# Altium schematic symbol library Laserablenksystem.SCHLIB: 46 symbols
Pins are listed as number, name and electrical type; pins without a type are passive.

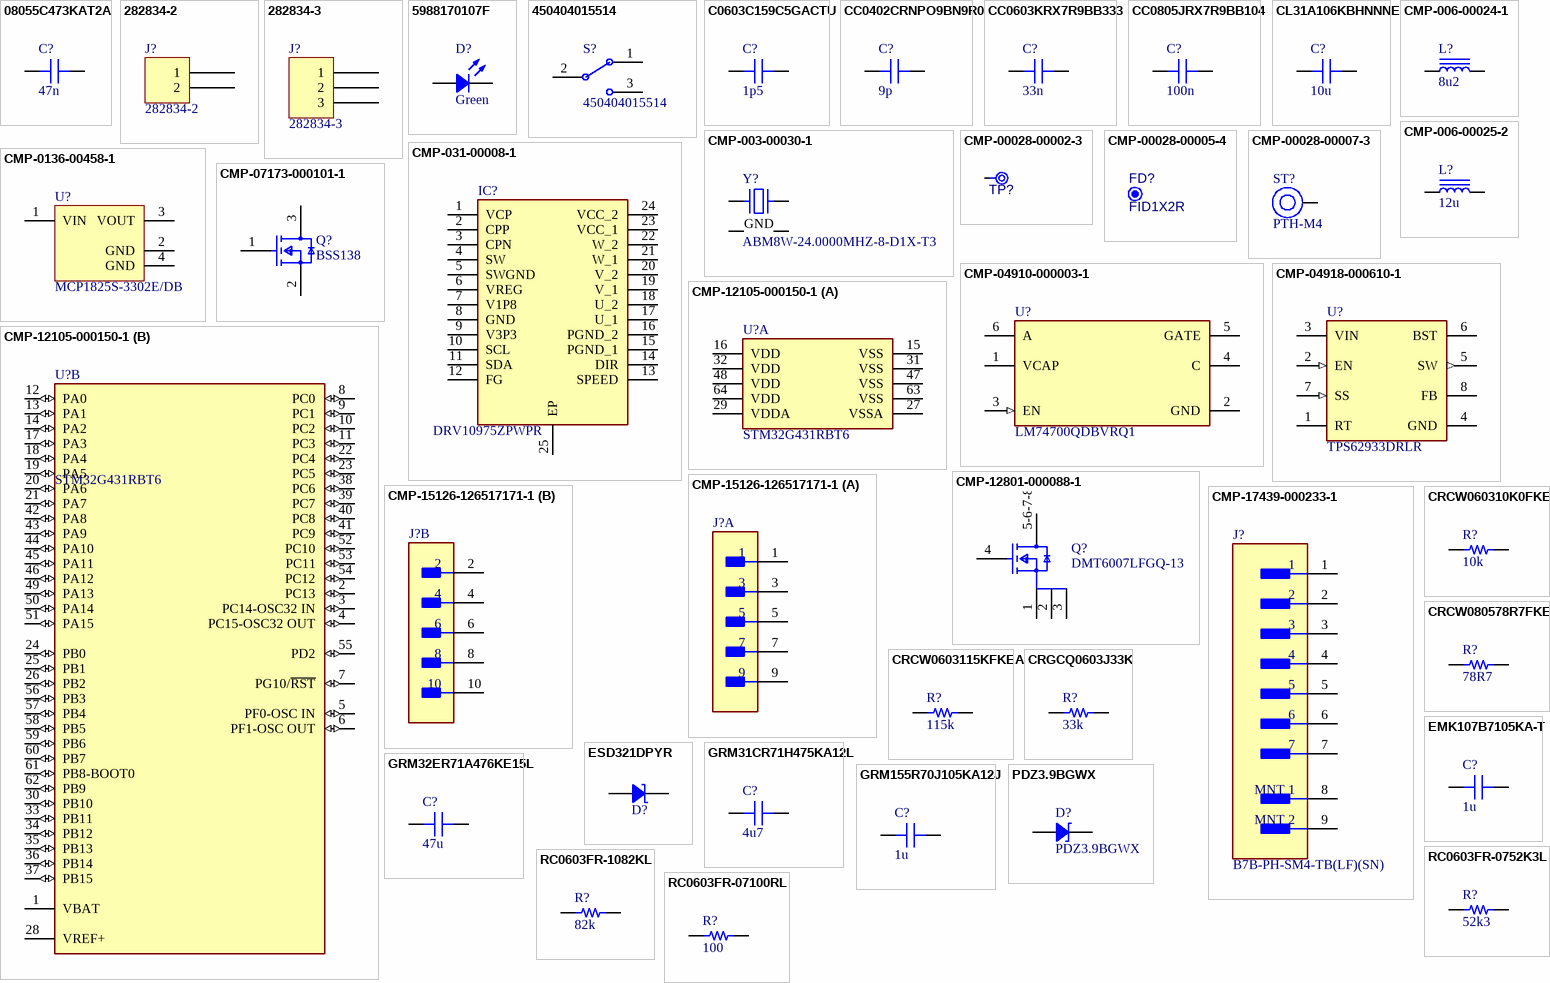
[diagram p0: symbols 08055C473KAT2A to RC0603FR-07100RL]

## 08055C473KAT2A
designator C?, comment Capacitance: 47n  (hidden comment: 0.047µF)
CAP CER 0.047UF 50V X7R 0805; Part Number: 08055C473KAT2A; manufacturer: AVX Corporation; Tolerance: ±10%
footprint CAP 0805_2012
pins: 1, 2

## 282834-2
designator J?
TERM BLK 2P SIDE ENT 2.54MM PCB; Manufacturer: TE Connectivity AMP Connectors; Current: 10A; Mating Orientation: Horizontal with Board; Number of Levels: 1; Pitch: 0.100" (2.54mm); Positions Per Level: 2; Voltage: 150V; Wire Gauge: 16-30 AWG; Wire Termination: Screw - Rising Cage Clamp
footprint TE 282834-2
pins: 1, 2

## 282834-3
designator J?
TERM BLK 3P SIDE ENT 2.54MM PCB; Manufacturer: TE Connectivity AMP Connectors; Current: 10A; Mating Orientation: Horizontal with Board; Number of Levels: 1; Pitch: 0.100" (2.54mm); Positions Per Level: 3; Voltage: 150V; Wire Gauge: 16-30 AWG; Wire Termination: Screw - Rising Cage Clamp
footprint TE 282834-3
pins: 1, 2, 3

## 5988170107F
designator D?, comment Green
LED GREEN CLEAR 0805 SMD; Part Number: 5988170107F; Manufacturer: Dialight; Configuration: Standard; Current - Test: 20mA; Lens Color: Colorless; Lens Size: 1.40mm x 1.25mm; Lens Style: Rectangle with Flat Top; Millicandela Rating: 20mcd; Viewing Angle: 140°; Voltage - Forward (Vf) (Typ): 2V; Wavelength - Dominant: 566nm
footprint LED 0805_2012 GREEN
pins: 1, 2

## 450404015514
designator S?
MINI SLIDE SWITCH 6.7 X 2.7 MM.; Manufacturer: Würth Elektronik; Rated Current: 300mA; Rated Voltage: 5VDC; Switching Function: On-On; Circuit: SPDT; Actuator Length: 1.50mm; Actuator Type: Standard; Contact Timing: Non-Shorting (BBM); Current Rating (Amps): 300mA (DC); Voltage Rating - DC: 5 V
footprint WURTH WS-SLSU 450404015514
pins: 1, 2 COM, 3

## C0603C159C5GACTU
designator C?, comment Capacitance: 1p5  (hidden comment: 1.5 pF)
CAP CER 1.5PF 50V C0G/NP0 0603; Part Number: C0603C159C5GACTU; manufacturer: KEMET; Temperature Coefficient: C0G, NP0; Tolerance: ±0.25pF
footprint CAP 0603_1608
pins: 1, 2

## CC0402CRNPO9BN9R0
designator C?, comment Capacitance: 9p  (hidden comment: 9 pF)
CAP CER 9PF 50V C0G/NPO 0402; Part Number: CC0402CRNPO9BN9R0; manufacturer: Yageo; Temperature Coefficient: C0G, NP0; Tolerance: ±0.25pF
footprint CAP 0402_1005
pins: 1, 2

## CC0603KRX7R9BB333
designator C?, comment Capacitance: 33n  (hidden comment: 0.033 µF)
CAP CER 0.033UF 50V X7R 0603; Part Number: CC0603KRX7R9BB333; manufacturer: Yageo; Tolerance: ±10%
footprint CAP 0603_1608
pins: 1, 2

## CC0805JRX7R9BB104
designator C?, comment Capacitance: 100n  (hidden comment: 0.1 µF)
CAP CER 0.1UF 50V X7R 0805; Part Number: CC0805JRX7R9BB104; manufacturer: Yageo; Tolerance: ±5%
footprint CAP 0805_2012
pins: 1, 2

## CL31A106KBHNNNE
designator C?, comment Capacitance: 10u  (hidden comment: 10 µF)
CAP CER 10UF 50V X5R 1206; Part Number: CL31A106KBHNNNE; manufacturer: Samsung Electro-Mechanics; Tolerance: ±10%
footprint CAP 1206_3216 - 0.8MM
pins: 1, 2

## CMP-003-00030-1
designator Y?, comment ABM8W-24.0000MHZ-8-D1X-T3
Crystal 24MHz ±10ppm (Tol) ±20ppm (Stability) 8pF FUND 50Ohm 4-Pin SMD T/R; Manufacturer: Abracon; ESR: 25; ESR (Equivalent Series Resistance): 50Ω; Tolerance: 0.001%
footprint FP-ABM8W-MFG
pins: 1, 2 GND, 3, 4 GND

## CMP-006-00024-1
designator L?, comment value 8u2  (hidden comment: IHLP5050EZER8R2M01)
Inductor Power Shielded Wirewound 8.2uH 20% 100KHz Powdered Iron 9.5A 0.0225Ohm DCR 5050 T/R; Manufacturer: Vishay; DC Resistance (DCR): 22.5mΩ; Core Material: Composite; Number of Circuits: 1; Saturation Current: 18A
footprint FP-IHLP-5050EZ-FP_3_226x4-MFG
pins: 1, 2

## CMP-006-00025-2
designator L?, comment value 12u  (hidden comment: SDR1307-120ML)
Inductor Power Unshielded Wirewound 12uH 20% 100KHz 25Q-Factor Ferrite 4.8A 0.03Ohm DCR T/R; Manufacturer_Name: Bourns; Q Factor: 25; Number of Circuits: 1; Saturation Current: 8A; Self Resonant Frequency: 20MHz; DC Resistance (DCR): 30mΩ
footprint SDR1307120ML
pins: 1, 2

## CMP-00028-00002-3
designator TP?, comment TPAD6R  (value not drawn)  (no BOM)
0.6mm round
footprint TP06R (Testpoint, round, d=0.6mm)
pins: 1 TP

## CMP-00028-00005-4
designator FD?, comment FID1X2R  (no BOM)
Fiducial - Round 1x2mm; Manufacturer: No Vendor
footprint FID1X2R (Fiducial - Round 1x2mm)
pins: 0

## CMP-00028-00007-3
designator ST?, comment PTH-M4  (no BOM)
M4 PTH (4.5mm), 7.5mm pad
footprint PTH-M4-Footprint
pins: 1 H1

## CMP-031-00008-1
designator IC?, comment DRV10975ZPWPR
Integrated Circuit; Manufacturer_Name: Texas Instruments
footprint SOP65P640X120-25N
pins: 1 VCP, 2 CPP, 3 CPN, 4 SW, 5 SWGND, 6 VREG, 7 V1P8, 8 GND, 9 V3P3, 10 SCL, 11 SDA, 12 FG, 13 SPEED, 14 DIR, 15 PGND_1, 16 PGND_2, 17 U_1, 18 U_2, 19 V_1, 20 V_2, 21 W_1, 22 W_2, 23 VCC_1, 24 VCC_2, 25 EP

## CMP-0136-00458-1
designator U?, comment MCP1825S-3302E/DB
500 mA, Low Voltage, Low Quiescent Current LDO Regulator, 3-Pin SOT-223, Extended Temperature
footprint SOT-223-DB3_N (SOT223, 4-Leads, Body 6.5x3.5mm, Pitch 2.3mm, Lead Span 7mm, IPC Medium Density)
footprint SOT-223-DB3_L (SOT223, 4-Leads, Body 6.5x3.5mm, Pitch 2.3mm, Lead Span 7mm, IPC High Density)
footprint SOT-223-DB3_M (SOT223, 4-Leads, Body 6.5x3.5mm, Pitch 2.3mm, Lead Span 7mm, IPC Low Density)
pins: 1 VIN (power), 2 GND (power), 3 VOUT (power), 4 GND (power)

## CMP-04910-000003-1
designator U?, comment LM74700QDBVRQ1
POWER MANAGEMENT; Manufacturer: Texas Instruments; Number Of Outputs: 1; Standoff Height: 0mm; Automotive Grade: Grade 1; Nominal Supply Current: 80uA; Max Junction Temp: +150°C; Max Supply Voltage: 65V; Min Supply Voltage: 3.2V
footprint FP-DBV0006A-MFG
footprint FP-DBV0006A-IPC_C
footprint FP-DBV0006A-IPC_B
footprint FP-DBV0006A-IPC_A
pins: 1 VCAP (power), 2 GND (power), 3 EN (in), 4 C, 5 GATE, 6 A

## CMP-04918-000610-1
designator U?, comment TPS62933DRLR
3.8-V to 30-V, 3-A, 200-kHz to 2.2-MHz, low-IQ synchronous buck converter in SOT-583 package 8-SOT-5X3 -40 to 150
footprint FP-DRL0008A-MFG
pins: 1 RT, 2 EN (in), 3 VIN (power), 4 GND (power), 5 SW (out), 6 BST, 7 SS (in), 8 FB

## CMP-07173-000101-1
designator Q?, comment BSS138
MOSFET N-CH 50V 220MA SOT-23; Turn-Off Delay Time: 20ns; Element Configuration: Single; Rds On Max: 3.5R; Gate to Source Voltage (Vgs): 20V; Threshold Voltage: 1.3V; Number of Elements: 1; Power Dissipation: 360mW; Rise Time: 9ns; Turn-On Delay Time: 2.5ns; Input Capacitance: 27pF; On-State Resistance: 6R
footprint FP-318-08-IPC_B
footprint FP-318-08-MFG
footprint FP-318-08-IPC_A
footprint FP-318-08-IPC_C
pins: 1 G, 2 S, 3 D

## CMP-12105-000150-1
designator U?, comment STM32G431RBT6
IC MCU 32BIT 128KB FLASH 64LQFP
footprint FP-LQFP64-5W-MFG
footprint FP-LQFP64-5W-IPC_B
footprint FP-LQFP64-5W-IPC_A
footprint FP-LQFP64-5W-IPC_C
part A pins: 15 VSS (power), 16 VDD (power), 27 VSSA (power), 29 VDDA (power), 31 VSS (power), 32 VDD (power), 47 VSS (power), 48 VDD (power), 63 VSS (power), 64 VDD (power)
part B pins: 1 VBAT (power), 2 PC13 (io), 3 PC14-OSC32 IN (io), 4 PC15-OSC32 OUT (io), 5 PF0-OSC IN (io), 6 PF1-OSC OUT (io), 7 PG10/~{RST} (io), 8 PC0 (io), 9 PC1 (io), 10 PC2 (io), 11 PC3 (io), 12 PA0 (io), 13 PA1 (io), 14 PA2 (io), 17 PA3 (io), 18 PA4 (io), 19 PA5 (io), 20 PA6 (io), 21 PA7 (io), 22 PC4 (io), 23 PC5 (io), 24 PB0 (io), 25 PB1 (io), 26 PB2 (io), 28 VREF+ (power), 30 PB10 (io), 33 PB11 (io), 34 PB12 (io), 35 PB13 (io), 36 PB14 (io), 37 PB15 (io), 38 PC6 (io), 39 PC7 (io), 40 PC8 (io), 41 PC9 (io), 42 PA8 (io), 43 PA9 (io), 44 PA10 (io), 45 PA11 (io), 46 PA12 (io), 49 PA13 (io), 50 PA14 (io), 51 PA15 (io), 52 PC10 (io), 53 PC11 (io), 54 PC12 (io), 55 PD2 (io), 56 PB3 (io), 57 PB4 (io), 58 PB5 (io), 59 PB6 (io), 60 PB7 (io), 61 PB8-BOOT0 (io), 62 PB9 (io)

## CMP-12801-000088-1
designator Q?, comment DMT6007LFGQ-13
MOSFET BVDSS: 41V-60V POWERDI333; Drain to Source Voltage (Vdss): 60V; Continuous Drain Current (ID): 80A; Input Capacitance: 2.09nF; Rds On Max: 6mR; Max Power Dissipation: 62.5W
footprint FP-POWERDI3333-8-MFG
pins: 1 S, 2 S, 3 S, 4 G, 5-6-7-8 D

## CMP-15126-126517171-1
designator J?, comment 20021121-00010C4LF  (value not drawn)
20021121-00010C4LF Conn Unshrouded Header HDR 10 POS 1.27mm Solder ST Top Entry SMD Minitek127® T/R; NexarPartId: 126517171; Current Rating: 1A; Voltage Rating: 125V; Number of Contacts: 10; Connector Type: Header, Male Pin; Mating Post Length: 3.05mm; Insulation Resistance: 100MΩ; Gender: Male; Contact Resistance: 30mΩ; Stack Height: 3mm
footprint FP-20021121-00010C4LF-MFG (Conn Unshrouded Header HDR 10 POS 1.27mm Solder ST Top Entry SMD Minitek127® T/R)
part A pins: 1, 3, 5, 7, 9
part B pins: 2, 4, 6, 8, 10

## CMP-17439-000233-1
designator J?, comment B7B-PH-SM4-TB(LF)(SN)
CONN HEADER SMD 7POS 2MM; Mated Stacking Heights: 8.6mm; Number of Poles: 7; Voltage Rating (AC): 100V; Contact Resistance: 20mR; Gender: Male; Current Rating: 2A; Insulation Resistance: 1GR
footprint FP-B7B-PH-SM4-TB_LF_SN-MFG
pins: 1, 2, 3, 4, 5, 6, 7, 8 MNT 1, 9 MNT 2

## CRCW060310K0FKEA
designator R?, comment 10k
RES SMD 10K OHM 1% 1/10W 0603; Part Number: CRCW060310K0FKEA; Manufacturer: Vishay Dale; Power (Watts): 0.1W, 1/10W; Resistance: 10 kOhms; Temperature Coefficient: ±100ppm/°C
footprint RES 0603_1608
pins: 1, 2

## CRCW080578R7FKEA
designator R?, comment 78R7
RES SMD 78.7 OHM 1% 1/8W 0805; Part Number: CRCW080578R7FKEA; Manufacturer: Vishay Dale; Power (Watts): 0.125W, 1/8W; Resistance: 78.7 Ohms; Temperature Coefficient: ±100ppm/°C
footprint RES 0805_2012
pins: 1, 2

## CRCW0603115KFKEA
designator R?, comment 115k
RES SMD 115K OHM 1% 1/10W 0603; Part Number: CRCW0603115KFKEA; Manufacturer: Vishay Dale; Power (Watts): 0.1W, 1/10W; Resistance: 115 kOhms; Temperature Coefficient: ±100ppm/°C
footprint RES 0603_1608
pins: 1, 2

## CRGCQ0603J33K
designator R?, comment 33k
RES 33K OHM 5% 1/10W 0603; Part Number: CRGCQ0603J33K; Manufacturer: TE Connectivity Passive Product; Power (Watts): 0.1W, 1/10W; Resistance: 33 kOhms; Temperature Coefficient: ±100ppm/°C
footprint RES 0603_1608
pins: 1, 2

## EMK107B7105KA-T
designator C?, comment Capacitance: 1u  (hidden comment: 1 µF)
CAP CER 1UF 16V X7R 0603; Part Number: EMK107B7105KA-T; manufacturer: Taiyo Yuden; Tolerance: ±10%
footprint CAP 0603_1608
pins: 1, 2

## ESD321DPYR
designator D?  (value not drawn)
TVS DIODE 3.6VWM 6.8VC 2X1SON; Manufacturer: Texas Instruments; Capacitance @ Frequency: 0.9pF @ 1MHz; Current - Peak Pulse (10/1000µs): 6A (8/20µs); Power Line Protection: No; Power - Peak Pulse: 40W; Type: Zener; Unidirectional Channels: 1; Voltage - Breakdown (Min): 4.5V; Voltage - Clamping (Max) @ Ipp: 6.8V (Typ); Voltage - Reverse Standoff (Typ): 3.6V (Max)
footprint 0402
pins: 1, 2

## GRM31CR71H475KA12L
designator C?, comment Capacitance: 4u7  (hidden comment: 4.7 µF)
CAP CER 4.7UF 50V X7R 1206; Part Number: GRM31CR71H475KA12L; manufacturer: Murata Electronics; Tolerance: ±10%
footprint CAP 1206_3216 - 0.8MM
pins: 1, 2

## GRM32ER71A476KE15L
designator C?, comment 47u
CAP CER 47UF 10V X7R 1210; Part Number: GRM32ER71A476KE15L; manufacturer: Murata Electronics; Capacitance: 47 µF; Tolerance: ±10%
footprint CAP 1210_3225 - 1MM
pins: 1, 2

## GRM155R70J105KA12J
designator C?, comment Capacitance: 1u  (hidden comment: 1 µF)
CAP CER 1UF 6.3V X7R 0402; Part Number: GRM155R70J105KA12J; manufacturer: Murata Electronics; Tolerance: ±10%
footprint CAP 0402_1005
pins: 1, 2

## PDZ3.9BGWX
designator D?
DIODE ZENER 3.9V 365MW SOD123W; Manufacturer: Nexperia USA Inc.; Current - Reverse Leakage @ Vr: 3 µA @ 1 V; Impedance (Max) (Zzt): 90 Ohms; Tolerance: ±2%; Voltage - Forward (Vf) (Max) @ If: 1.1 V @ 100 mA
footprint SOD-123
pins: 1, 2

## RC0603FR-0752K3L
designator R?, comment 52k3
RES 52.3K OHM 1% 1/10W 0603; Part Number: RC0603FR-0752K3L; Manufacturer: Yageo; Power (Watts): 0.1W, 1/10W; Resistance: 52.3 kOhms; Temperature Coefficient: ±100ppm/°C
footprint RES 0603_1608
pins: 1, 2

## RC0603FR-1082KL
designator R?, comment 82k
RES 82K OHM 1% 1/10W 0603; Part Number: RC0603FR-1082KL; Manufacturer: Yageo; Power (Watts): 0.1W, 1/10W; Resistance: 82 kOhms; Temperature Coefficient: ±100ppm/°C
footprint RES 0603_1608
pins: 1, 2

## RC0603FR-07100RL
designator R?, comment 100
RES 100 OHM 1% 1/10W 0603; Part Number: RC0603FR-07100RL; Manufacturer: Yageo; Power (Watts): 0.1W, 1/10W; Resistance: 100 Ohms; Temperature Coefficient: ±100ppm/°C
footprint RES 0603_1608
pins: 1, 2

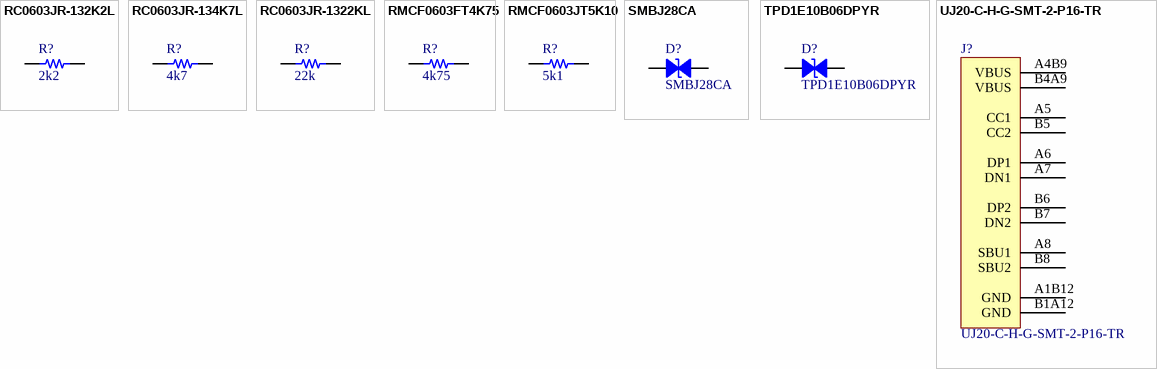
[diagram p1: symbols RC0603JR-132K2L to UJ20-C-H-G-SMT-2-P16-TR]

## RC0603JR-132K2L
designator R?, comment 2k2
RES 2.2K OHM 5% 1/10W 0603; Part Number: RC0603JR-132K2L; Manufacturer: Yageo; Power (Watts): 0.1W, 1/10W; Resistance: 2.2 kOhms; Temperature Coefficient: ±100ppm/°C
footprint RES 0603_1608
pins: 1, 2

## RC0603JR-134K7L
designator R?, comment 4k7
RES 4.7K OHM 5% 1/10W 0603; Part Number: RC0603JR-134K7L; Manufacturer: Yageo; Power (Watts): 0.1W, 1/10W; Resistance: 4.7 kOhms; Temperature Coefficient: ±100ppm/°C
footprint RES 0603_1608
pins: 1, 2

## RC0603JR-1322KL
designator R?, comment 22k
RES 22K OHM 5% 1/10W 0603; Part Number: RC0603JR-1322KL; Manufacturer: Yageo; Power (Watts): 0.1W, 1/10W; Resistance: 22 kOhms; Temperature Coefficient: ±100ppm/°C
footprint RES 0603_1608
pins: 1, 2

## RMCF0603FT4K75
designator R?, comment 4k75
RES 4.75K OHM 1% 1/10W 0603; Part Number: RMCF0603FT4K75; Manufacturer: Stackpole Electronics Inc; Power (Watts): 0.1W, 1/10W; Resistance: 4.75 kOhms; Temperature Coefficient: ±100ppm/°C
footprint RES 0603_1608
pins: 1, 2

## RMCF0603JT5K10
designator R?, comment 5k1
RES 5.1K OHM 5% 1/10W 0603; Part Number: RMCF0603JT5K10; Manufacturer: Stackpole Electronics Inc; Power (Watts): 0.1W, 1/10W; Resistance: 5.1 kOhms; Temperature Coefficient: ±200ppm/°C
footprint RES 0603_1608
pins: 1, 2

## SMBJ28CA
designator D?
TVS DIODE 28VWM 45.4VC DO214AA; Manufacturer: Littelfuse Inc.; Bidirectional Channels: 1; Current - Peak Pulse (10/1000µs): 13.3A; Power Line Protection: No; Power - Peak Pulse: 600W; Type: Zener; Voltage - Breakdown (Min): 31.1V; Voltage - Clamping (Max) @ Ipp: 45.4V; Voltage - Reverse Standoff (Typ): 28V
footprint DO214AA SMB
pins: 1, 2

## TPD1E10B06DPYR
designator D?
TVS DIODE 5.5VWM 14VC 2X1SON; Manufacturer: Texas Instruments; Bidirectional Channels: 1; Current - Peak Pulse (10/1000µs): 5A (8/20µs); Power Line Protection: No; Power - Peak Pulse: 90W; Type: Zener; Voltage - Breakdown (Min): 6V; Voltage - Clamping (Max) @ Ipp: 14V; Voltage - Reverse Standoff (Typ): 5.5V (Max)
footprint 0402
pins: 1, 2

## UJ20-C-H-G-SMT-2-P16-TR
designator J?
CONN RCPT USB 2.0 TYPE C SMD RA; Manufacturer: Same Sky (Formerly CUI Devices); Connector Type: USB-C (USB TYPE-C); Current Rating (Amps): 0.25A, 1.25A, 5A; Gender: Receptacle; Mating Cycles: 10000; Number of Contacts: 24 (16+8 Dummy); Number of Ports: 1; Shielding: Shielded; Specifications: USB 2.0
footprint Same Sky UJ20-C-H-G-SMT-2-P16-TR
pins: A1B12 GND, A4B9 VBUS, A5 CC1, A6 DP1, A7 DN1, A8 SBU1, B1A12 GND, B4A9 VBUS, B5 CC2, B6 DP2, B7 DN2, B8 SBU2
